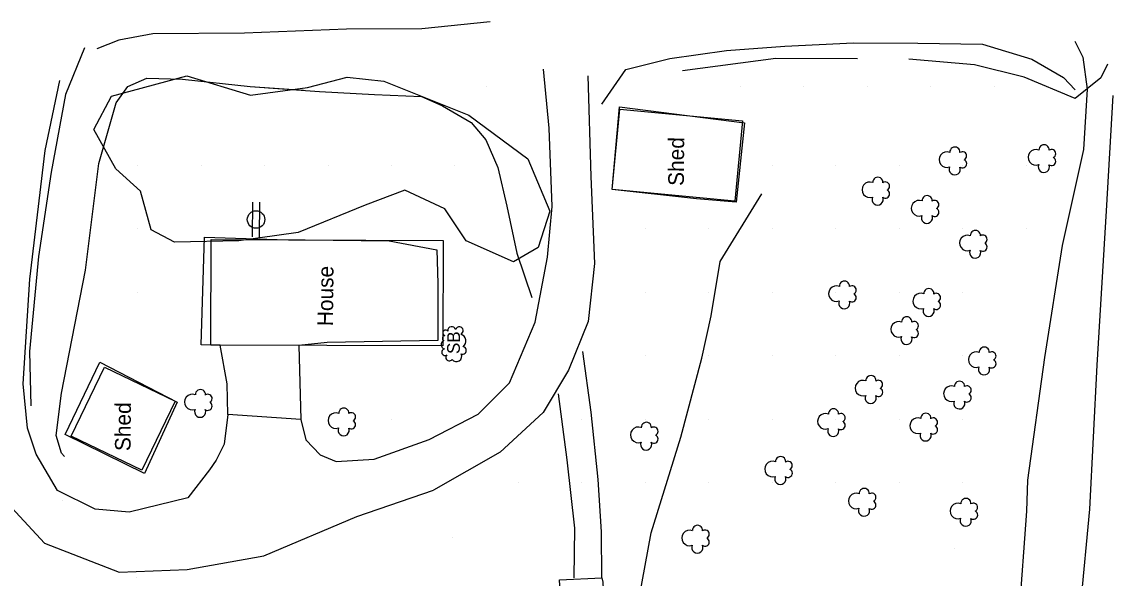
# Model space of a CAD drawing. Extents: x 19528164 to 19545171, y 7585743 to 7602745.
# Drawn here: x 19539508.5 to 19539852.4, y 7595364.9 to 7595540.3 of the extents above; entities that cross this region are included whole.
import ezdxf

# ---------------------------------------------------------------- set-up
doc = ezdxf.new("R2010")
doc.units = 0
for name, color, linetype in [('PhoBreakLine', 7, 'Continuous'), ('PhoBuilding', 7, 'Continuous'), ('PhoDrainageArrow', 7, 'Continuous'), ('PhoEdgeEntrancePaved', 7, 'Continuous'), ('PhoISAEPoints', 7, 'Continuous'), ('PhoNotesDesign', 7, 'Continuous'), ('PhoTerrace', 7, 'Continuous'), ('PhoVegetation', 7, 'Continuous'), ('SurBreakLine', 7, 'Continuous'), ('SurEdgeEntranceUnpaved', 7, 'Continuous'), ('SurNaturalCells', 7, 'Continuous'), ('SurROWRail', 7, 'Continuous')]:
    doc.layers.add(name, color=color, linetype=linetype)

msp = doc.modelspace()

# ---------------------------------------------------------------- linework, layer by layer
at = {"layer": 'PhoBreakLine'}
for points in [[(19539656.14, 7595540.26), (19539634.56, 7595538.05), (19539610.86, 7595537.93), (19539578.71, 7595536.73), (19539549.77, 7595536.45), (19539539.03, 7595534.45), (19539532.18, 7595531.7)], [(19539528.27, 7595532.08), (19539522.26, 7595517.34), (19539517.79, 7595492.87), (19539513.77, 7595466.3), (19539510.93, 7595436.35), (19539511.31, 7595419.16)], [(19539691.32, 7595514.29), (19539698.89, 7595525.2), (19539712.75, 7595528.74), (19539730.58, 7595531.21), (19539748.91, 7595532.55), (19539770.57, 7595533.66), (19539790.89, 7595533.48), (19539811.26, 7595533.17), (19539826.76, 7595528.51), (19539836.79, 7595522.69), (19539840.45, 7595518.84)], [(19539521.95, 7595403.18), (19539520.98, 7595404.28), (19539519.31, 7595409.86), (19539521.01, 7595423.21), (19539528.56, 7595461.98), (19539532.8, 7595495.58), (19539538.26, 7595514.75), (19539541.87, 7595519.9), (19539547.93, 7595522.49), (19539559.17, 7595522.21), (19539580.47, 7595519.88), (19539602.35, 7595518.32), (19539619.61, 7595517.35), (19539634.42, 7595516.76), (19539641.11, 7595513.75), (19539650.09, 7595508.47), (19539654.74, 7595503.08), (19539658.56, 7595494.33), (19539661.33, 7595482.18), (19539664.54, 7595467.32), (19539669.21, 7595453.4)], [(19539521.95, 7595403.18), (19539520.98, 7595404.28), (19539519.31, 7595409.86), (19539521.01, 7595423.21), (19539528.56, 7595461.98), (19539532.8, 7595495.58), (19539538.26, 7595514.75), (19539541.87, 7595519.9), (19539547.93, 7595522.49), (19539559.17, 7595522.21), (19539580.47, 7595519.88), (19539602.35, 7595518.32), (19539619.61, 7595517.35), (19539634.42, 7595516.76), (19539641.11, 7595513.75), (19539650.09, 7595508.47), (19539654.74, 7595503.08), (19539658.56, 7595494.33), (19539661.33, 7595482.18), (19539664.54, 7595467.32), (19539669.21, 7595453.4)], [(19539639.33, 7595468.39), (19539639.58, 7595457.72), (19539639.61, 7595439.84), (19539604.76, 7595439.12), (19539595.78, 7595438.24), (19539571.06, 7595438.33), (19539565.03, 7595438.41), (19539566.04, 7595472.32), (19539588.94, 7595471.63), (19539624.3, 7595471.25), (19539639.33, 7595468.39)]]:
    msp.add_lwpolyline(points, dxfattribs=at)
for points in [[(19539736.23, 7595508.41), (19539733.62, 7595483.44), (19539721.09, 7595484.43), (19539694.59, 7595487.36), (19539696.86, 7595513.43)], [(19539522.2, 7595410.17), (19539533.07, 7595432.93), (19539557.48, 7595420.37), (19539547.13, 7595397.82)], [(19539522.2, 7595410.17), (19539533.07, 7595432.93), (19539557.48, 7595420.37), (19539547.13, 7595397.82)]]:
    msp.add_lwpolyline(points, close=True, dxfattribs=at)
at = {"layer": 'PhoBuilding'}
for points in [[(19539696.96, 7595512.7), (19539735.6, 7595509), (19539733.18, 7595483.67), (19539694.54, 7595487.37)], [(19539568.21, 7595471.63), (19539641.3, 7595471.37), (19539641.18, 7595438.08), (19539568.09, 7595438.34)], [(19539534.59, 7595431.42), (19539556.87, 7595420.63), (19539546.34, 7595398.87), (19539524.05, 7595409.65)], [(19539534.59, 7595431.42), (19539556.87, 7595420.63), (19539546.34, 7595398.87), (19539524.05, 7595409.65)]]:
    msp.add_lwpolyline(points, close=True, dxfattribs=at)
at = {"layer": 'PhoDrainageArrow'}
msp.add_lwpolyline([(19539840.3, 7595534.21), (19539842.9, 7595529.15), (19539844.21, 7595518.99), (19539843.09, 7595500.03), (19539836.39, 7595469.78), (19539830.77, 7595434.44), (19539825.41, 7595395.73), (19539825.08, 7595385.99)], dxfattribs=at)
msp.add_lwpolyline([(19539840.3, 7595534.21), (19539842.9, 7595529.15), (19539844.21, 7595518.99), (19539843.09, 7595500.03), (19539836.39, 7595469.78), (19539830.77, 7595434.44), (19539825.41, 7595395.73), (19539825.08, 7595385.99)], dxfattribs=at)
at = {"layer": 'PhoEdgeEntrancePaved'}
msp.add_lwpolyline([(19539595.78, 7595438.24), (19539596.42, 7595414.85), (19539573.4, 7595416.42), (19539573.23, 7595426.17), (19539571.06, 7595438.33)], dxfattribs=at)
msp.add_lwpolyline([(19539691.58, 7595363.55), (19539692.41, 7595345.9), (19539692.02, 7595329.56), (19539689.73, 7595299.93), (19539673.78, 7595300.14), (19539675.32, 7595315.13), (19539676.3, 7595326.05), (19539678.13, 7595336.3), (19539679.5, 7595338.73), (19539677.96, 7595364.29), (19539691.28, 7595364.99)], close=True, dxfattribs=at)
at = {"layer": 'PhoISAEPoints'}
for p, q in [((19539655, 7595520), (19539655, 7595520)), ((19539735, 7595520), (19539735, 7595520)), ((19539755, 7595520), (19539755, 7595520)), ((19539775, 7595520), (19539775, 7595520)), ((19539795, 7595520), (19539795, 7595520)), ((19539815, 7595520), (19539815, 7595520)), ((19539545, 7595495), (19539545, 7595495)), ((19539565, 7595495), (19539565, 7595495)), ((19539585.04, 7595495), (19539585.04, 7595495)), ((19539605, 7595495), (19539605, 7595495)), ((19539625, 7595495), (19539625, 7595495)), ((19539645, 7595495), (19539645, 7595495)), ((19539745, 7595495), (19539745, 7595495)), ((19539765, 7595495), (19539765, 7595495)), ((19539785, 7595495), (19539785, 7595495)), ((19539805, 7595495), (19539805, 7595495)), ((19539825, 7595495), (19539825, 7595495)), ((19539545, 7595475), (19539545, 7595475)), ((19539705, 7595475), (19539705, 7595475)), ((19539725, 7595475), (19539725, 7595475)), ((19539745, 7595475), (19539745, 7595475)), ((19539765, 7595475), (19539765, 7595475)), ((19539785, 7595475), (19539785, 7595475)), ((19539805, 7595475), (19539805, 7595475)), ((19539825, 7595475), (19539825, 7595475)), ((19539545, 7595455), (19539545, 7595455)), ((19539705, 7595455), (19539705, 7595455)), ((19539725, 7595455), (19539725, 7595455)), ((19539745, 7595455), (19539745, 7595455)), ((19539765, 7595455), (19539765, 7595455)), ((19539785, 7595455), (19539785, 7595455)), ((19539805, 7595455), (19539805, 7595455)), ((19539705, 7595435), (19539705, 7595435)), ((19539725, 7595435), (19539725, 7595435)), ((19539745, 7595435), (19539745, 7595435)), ((19539765, 7595435), (19539765, 7595435)), ((19539785, 7595435), (19539785, 7595435)), ((19539805, 7595435), (19539805, 7595435)), ((19539625, 7595415), (19539625, 7595415)), ((19539685, 7595415), (19539685, 7595415)), ((19539705, 7595415), (19539705, 7595415)), ((19539725, 7595415), (19539725, 7595415)), ((19539745, 7595415), (19539745, 7595415)), ((19539765, 7595415), (19539765, 7595415)), ((19539785, 7595415), (19539785, 7595415)), ((19539805, 7595415), (19539805, 7595415)), ((19539665, 7595395), (19539665, 7595395)), ((19539665, 7595395), (19539665, 7595395)), ((19539685, 7595395), (19539685, 7595395)), ((19539685, 7595395), (19539685, 7595395)), ((19539705, 7595395), (19539705, 7595395)), ((19539705, 7595395), (19539705, 7595395)), ((19539725, 7595395), (19539725, 7595395)), ((19539725, 7595395), (19539725, 7595395)), ((19539745, 7595395), (19539745, 7595395)), ((19539745, 7595395), (19539745, 7595395)), ((19539765, 7595395), (19539765, 7595395)), ((19539765, 7595395), (19539765, 7595395)), ((19539785, 7595395), (19539785, 7595395)), ((19539785, 7595395), (19539785, 7595395)), ((19539805, 7595395), (19539805, 7595395))]:
    msp.add_line(p, q, dxfattribs=at)
at = {"layer": 'PhoTerrace'}
msp.add_lwpolyline([(19539845.06, 7595386.63), (19539847.38, 7595432.02), (19539850.38, 7595480.63), (19539852.43, 7595517.07)], dxfattribs=at)
msp.add_lwpolyline([(19539845.06, 7595386.63), (19539847.38, 7595432.02), (19539850.38, 7595480.63), (19539852.43, 7595517.07)], dxfattribs=at)
at = {"layer": 'PhoVegetation'}
for points in [[(19539771.9, 7595528.63), (19539746.11, 7595528.67), (19539716.68, 7595524.86)], [(19539850.63, 7595526.9), (19539848.56, 7595522.56), (19539840.48, 7595516.06), (19539824.35, 7595522.83), (19539808.7, 7595526.71), (19539788.03, 7595528.51)]]:
    msp.add_lwpolyline(points, dxfattribs=at)
msp.add_lwpolyline([(19539622.6, 7595521.55), (19539649.43, 7595510.88), (19539668.01, 7595497.04), (19539674.87, 7595480.6), (19539671.27, 7595469.15), (19539663.47, 7595464.57), (19539648.52, 7595471.24), (19539641.79, 7595481.29), (19539629.19, 7595487.19), (19539616.71, 7595482.5), (19539595.57, 7595473.81), (19539576.91, 7595471.17), (19539556.66, 7595470.78), (19539549.24, 7595474.73), (19539545.86, 7595486.88), (19539538.13, 7595493.93), (19539531.21, 7595506.26), (19539536.77, 7595516.81), (19539560.46, 7595523.19), (19539580.62, 7595517.16), (19539598.49, 7595519.59), (19539611.08, 7595522.83)], close=True, dxfattribs=at)
for centre, radius, start, end in [((19539830.64, 7595499.91), 1.6, 355.2463, 183.2499), ((19539800.02, 7595496.82), 2.46, 67.4531, 291.043), ((19539802.56, 7595499.19), 1.6, 355.2463, 183.2499), ((19539804.92, 7595497.95), 1.34, 295.7722, 124.6514), ((19539828.09, 7595497.55), 2.46, 67.4531, 291.043), ((19539833, 7595496.26), 1.34, 231.9982, 64.5704), ((19539833, 7595498.68), 1.34, 295.7722, 124.6514), ((19539802.49, 7595493.77), 1.76, 154.7305, 23.7656), ((19539804.93, 7595495.54), 1.34, 231.9982, 64.5704), ((19539830.57, 7595494.5), 1.76, 154.7305, 23.7656), ((19539778.28, 7595489.67), 1.6, 355.2463, 183.2499), ((19539775.74, 7595487.3), 2.46, 67.4531, 291.043), ((19539780.64, 7595486.02), 1.34, 231.9982, 64.5704), ((19539780.64, 7595488.44), 1.34, 295.7722, 124.6514), ((19539778.21, 7595484.26), 1.76, 154.7305, 23.7656), ((19539791.27, 7595481.5), 2.46, 67.4531, 291.043), ((19539793.81, 7595483.87), 1.6, 355.2463, 183.2499), ((19539796.17, 7595482.64), 1.34, 295.7722, 124.6514), ((19539796.17, 7595480.22), 1.34, 231.9982, 64.5704), ((19539793.74, 7595478.46), 1.76, 154.7305, 23.7656), ((19539809.01, 7595472.91), 1.6, 355.2463, 183.2499), ((19539806.47, 7595470.55), 2.46, 67.4531, 291.043), ((19539811.38, 7595469.27), 1.34, 231.9982, 64.5704), ((19539811.37, 7595471.68), 1.34, 295.7722, 124.6514), ((19539808.94, 7595467.5), 1.76, 154.7305, 23.7656), ((19539765.21, 7595454.57), 2.46, 67.4531, 291.043), ((19539767.75, 7595456.93), 1.6, 355.2463, 183.2499), ((19539770.11, 7595455.7), 1.34, 295.7722, 124.6514), ((19539794.35, 7595454.57), 1.6, 355.2463, 183.2499), ((19539770.12, 7595453.29), 1.34, 231.9982, 64.5704), ((19539791.8, 7595452.21), 2.46, 67.4531, 291.043), ((19539796.7, 7595453.34), 1.34, 295.7722, 124.6514), ((19539767.68, 7595451.52), 1.76, 154.7305, 23.7656), ((19539794.27, 7595449.16), 1.76, 154.7305, 23.7656), ((19539796.71, 7595450.93), 1.34, 231.9982, 64.5704), ((19539784.83, 7595443.32), 2.46, 67.4531, 291.043), ((19539787.37, 7595445.68), 1.6, 355.2463, 183.2499), ((19539789.73, 7595444.45), 1.34, 295.7722, 124.6514), ((19539642.05, 7595442.19), 0.9, 40.6417, 255.6594), ((19539644.03, 7595442.86), 1.3, 20.1519, 183.6168), ((19539646.37, 7595442.87), 1.21, 294.0775, 159.1351), ((19539789.74, 7595442.04), 1.34, 231.9982, 64.5704), ((19539642.05, 7595438.48), 1.41, 111.8517, 255.0316), ((19539641.82, 7595440.52), 0.794, 89.7085, 248.0319), ((19539646.2, 7595439.6), 2.27, 309.2663, 72.9457), ((19539787.3, 7595440.27), 1.76, 154.7305, 23.7656), ((19539641.86, 7595436.1), 1.04, 99.8428, 303.6092), ((19539645.47, 7595434.81), 1.67, 215.0769, 28.5329), ((19539647.41, 7595436.69), 1.18, 246.2738, 79.0083), ((19539809.26, 7595433.75), 2.46, 67.4531, 291.043), ((19539811.81, 7595436.11), 1.6, 355.2463, 183.2499), ((19539814.17, 7595434.88), 1.34, 295.7722, 124.6514), ((19539643.2, 7595434.46), 1.09, 134.5935, 326.0554), ((19539814.17, 7595432.47), 1.34, 231.9982, 64.5704), ((19539776.1, 7595427.14), 1.6, 355.2463, 183.2499), ((19539811.74, 7595430.7), 1.76, 154.7305, 23.7656), ((19539773.55, 7595424.77), 2.46, 67.4531, 291.043), ((19539778.45, 7595425.91), 1.34, 295.7722, 124.6514), ((19539801.47, 7595423.01), 2.46, 67.4531, 291.043), ((19539804.02, 7595425.37), 1.6, 355.2463, 183.2499), ((19539806.37, 7595424.14), 1.34, 295.7722, 124.6514), ((19539562.24, 7595420.38), 2.46, 67.4531, 291.043), ((19539564.79, 7595422.74), 1.6, 355.2463, 183.2499), ((19539567.15, 7595421.51), 1.34, 295.7722, 124.6514), ((19539776.03, 7595421.73), 1.76, 154.7305, 23.7656), ((19539778.46, 7595423.49), 1.34, 231.9982, 64.5704), ((19539806.38, 7595421.73), 1.34, 231.9982, 64.5704), ((19539567.15, 7595419.1), 1.34, 231.9982, 64.5704), ((19539610, 7595416.9), 1.6, 355.2463, 183.2499), ((19539764.3, 7595416.67), 1.6, 355.2463, 183.2499), ((19539803.95, 7595419.96), 1.76, 154.7305, 23.7656), ((19539564.72, 7595417.33), 1.76, 154.7305, 23.7656), ((19539607.46, 7595414.54), 2.46, 67.4531, 291.043), ((19539612.36, 7595415.67), 1.34, 295.7722, 124.6514), ((19539761.75, 7595414.31), 2.46, 67.4531, 291.043), ((19539766.65, 7595415.44), 1.34, 295.7722, 124.6514), ((19539790.85, 7595412.92), 2.46, 67.4531, 291.043), ((19539793.39, 7595415.28), 1.6, 355.2463, 183.2499), ((19539795.75, 7595414.05), 1.34, 295.7722, 124.6514), ((19539609.93, 7595411.49), 1.76, 154.7305, 23.7656), ((19539612.36, 7595413.26), 1.34, 231.9982, 64.5704), ((19539702.77, 7595410.04), 2.46, 67.4531, 291.043), ((19539705.32, 7595412.4), 1.6, 355.2463, 183.2499), ((19539707.68, 7595411.17), 1.34, 295.7722, 124.6514), ((19539764.22, 7595411.26), 1.76, 154.7305, 23.7656), ((19539766.66, 7595413.02), 1.34, 231.9982, 64.5704), ((19539795.76, 7595411.64), 1.34, 231.9982, 64.5704), ((19539707.68, 7595408.75), 1.34, 231.9982, 64.5704), ((19539793.32, 7595409.87), 1.76, 154.7305, 23.7656), ((19539705.25, 7595406.99), 1.76, 154.7305, 23.7656), ((19539745.08, 7595399.25), 2.46, 67.4531, 291.043), ((19539745.08, 7595399.25), 2.46, 67.4531, 291.043), ((19539747.63, 7595401.61), 1.6, 355.2463, 183.2499), ((19539747.63, 7595401.61), 1.6, 355.2463, 183.2499), ((19539749.98, 7595400.38), 1.34, 295.7722, 124.6514), ((19539749.98, 7595400.38), 1.34, 295.7722, 124.6514), ((19539749.99, 7595397.97), 1.34, 231.9982, 64.5704), ((19539749.99, 7595397.97), 1.34, 231.9982, 64.5704), ((19539747.55, 7595396.2), 1.76, 154.7305, 23.7656), ((19539747.55, 7595396.2), 1.76, 154.7305, 23.7656), ((19539771.44, 7595389.2), 2.46, 67.4531, 291.043), ((19539771.44, 7595389.2), 2.46, 67.4531, 291.043), ((19539773.99, 7595391.56), 1.6, 355.2463, 183.2499), ((19539773.99, 7595391.56), 1.6, 355.2463, 183.2499), ((19539776.34, 7595390.33), 1.34, 295.7722, 124.6514), ((19539776.34, 7595390.33), 1.34, 295.7722, 124.6514), ((19539776.35, 7595387.92), 1.34, 231.9982, 64.5704), ((19539776.35, 7595387.92), 1.34, 231.9982, 64.5704), ((19539803.49, 7595386.04), 2.46, 67.4531, 291.043), ((19539806.03, 7595388.41), 1.6, 355.2463, 183.2499), ((19539808.39, 7595387.17), 1.34, 295.7722, 124.6514), ((19539773.91, 7595386.15), 1.76, 154.7305, 23.7656), ((19539773.91, 7595386.15), 1.76, 154.7305, 23.7656), ((19539808.4, 7595384.76), 1.34, 231.9982, 64.5704), ((19539721.46, 7595379.93), 1.6, 355.2463, 183.2499), ((19539805.96, 7595383), 1.76, 154.7305, 23.7656), ((19539718.92, 7595377.56), 2.46, 67.4531, 291.043), ((19539723.82, 7595376.28), 1.34, 231.9982, 64.5704), ((19539723.82, 7595378.69), 1.34, 295.7722, 124.6514), ((19539721.39, 7595374.52), 1.76, 154.7305, 23.7656)]:
    msp.add_arc(centre, radius, start, end, dxfattribs=at)
at = {"layer": 'SurBreakLine'}
for points in [[(19539840.3, 7595534.21), (19539842.9, 7595529.15), (19539844.21, 7595518.99), (19539843.09, 7595500.03), (19539836.39, 7595469.78), (19539830.77, 7595434.44), (19539825.41, 7595395.73), (19539825.08, 7595385.99)], [(19539521.95, 7595403.18), (19539520.98, 7595404.28), (19539519.31, 7595409.86), (19539521.01, 7595423.21), (19539528.56, 7595461.98), (19539532.8, 7595495.58), (19539538.26, 7595514.75), (19539541.87, 7595519.9), (19539547.93, 7595522.49), (19539559.17, 7595522.21), (19539580.47, 7595519.88), (19539597.26, 7595518.68)], [(19539845.06, 7595386.63), (19539847.38, 7595432.02), (19539850.38, 7595480.63), (19539852.43, 7595517.07)], [(19539702.3, 7595318.13), (19539700.95, 7595347.07), (19539706.8, 7595379.19), (19539716.15, 7595409.28), (19539722.76, 7595434.24), (19539725.77, 7595447.54), (19539728.58, 7595464.72), (19539741.69, 7595486.07)], [(19539573.4, 7595416.42), (19539572.23, 7595407.08), (19539569.76, 7595402.08), (19539567.67, 7595399.02)], [(19539825.08, 7595385.99), (19539822.75, 7595352.96), (19539821.71, 7595273.61), (19539817.74, 7595207.38), (19539816.4, 7595164.27), (19539818.83, 7595146.42)], [(19539831, 7595141.37), (19539837.69, 7595218.67), (19539840.34, 7595295.59), (19539842.26, 7595356.59), (19539845.06, 7595386.63)]]:
    msp.add_lwpolyline(points, dxfattribs=at)
msp.add_lwpolyline([(19539522.2, 7595410.17), (19539533.07, 7595432.93), (19539557.48, 7595420.37), (19539547.13, 7595397.82)], close=True, dxfattribs=at)
at = {"layer": 'SurEdgeEntranceUnpaved'}
for p, q in [((19539665, 7595395), (19539665, 7595395)), ((19539685, 7595395), (19539685, 7595395)), ((19539705, 7595395), (19539705, 7595395)), ((19539725, 7595395), (19539725, 7595395)), ((19539745, 7595395), (19539745, 7595395)), ((19539765, 7595395), (19539765, 7595395)), ((19539785, 7595395), (19539785, 7595395)), ((19539521.28, 7595389.49), (19539521.28, 7595389.49)), ((19539644.2, 7595377.55), (19539644.2, 7595377.55)), ((19539802.53, 7595374.13), (19539802.53, 7595374.13)), ((19539544.63, 7595365.09), (19539544.63, 7595365.09))]:
    msp.add_line(p, q, dxfattribs=at)
at = {"layer": 'SurNaturalCells'}
for p, q in [((19539581.16, 7595472.44), (19539581.3, 7595483.43)), ((19539583.36, 7595472.41), (19539583.5, 7595483.4))]:
    msp.add_line(p, q, dxfattribs=at)
msp.add_circle((19539582.33, 7595477.92), 2.76, dxfattribs=at)
at = {"layer": 'SurROWRail'}
for points in [[(19539596.42, 7595414.85), (19539598, 7595408.49), (19539602.57, 7595403.71), (19539607.61, 7595401.63), (19539619.56, 7595402.43), (19539636.86, 7595408.55), (19539652.31, 7595416.56), (19539662.24, 7595426.44), (19539670.31, 7595445.62), (19539674.12, 7595466.11), (19539675.6, 7595482.05), (19539674.7, 7595506.72), (19539672.88, 7595525.33)], [(19539596.42, 7595414.85), (19539598, 7595408.49), (19539602.57, 7595403.71), (19539607.61, 7595401.63), (19539619.56, 7595402.43), (19539636.86, 7595408.55), (19539652.31, 7595416.56), (19539662.24, 7595426.44), (19539670.31, 7595445.62), (19539674.12, 7595466.11), (19539675.6, 7595482.05), (19539674.7, 7595506.72), (19539672.88, 7595525.33)], [(19539513.01, 7595404), (19539510.28, 7595412.13), (19539508.89, 7595426.18), (19539511.03, 7595459.16), (19539515.85, 7595499.67), (19539520.51, 7595521.77)], [(19539513.01, 7595404), (19539510.28, 7595412.13), (19539508.89, 7595426.18), (19539511.03, 7595459.16), (19539515.85, 7595499.67), (19539520.51, 7595521.77)], [(19539686.93, 7595523.21), (19539687.78, 7595491.46), (19539689, 7595464.08), (19539687.01, 7595445.75), (19539680.74, 7595430.44), (19539672.78, 7595417.04), (19539659.24, 7595404.54), (19539638.23, 7595392.61)], [(19539686.93, 7595523.21), (19539687.78, 7595491.46), (19539689, 7595464.08), (19539687.01, 7595445.75), (19539680.74, 7595430.44), (19539672.78, 7595417.04), (19539659.24, 7595404.54), (19539638.23, 7595392.61)], [(19539691.28, 7595364.99), (19539691.17, 7595379.44), (19539690.16, 7595395.97), (19539687.98, 7595417.2), (19539685.35, 7595436.34)], [(19539682.59, 7595364.93), (19539682.79, 7595380.6), (19539680.38, 7595402.16), (19539677.66, 7595423.02)], [(19539573.4, 7595416.42), (19539572.23, 7595407.08), (19539569.76, 7595402.08), (19539567.67, 7595399.02)], [(19539573.4, 7595416.42), (19539572.23, 7595407.08), (19539569.76, 7595402.08), (19539567.67, 7595399.02)], [(19539494.02, 7595407.99), (19539502.74, 7595389.83), (19539515.61, 7595375.88), (19539539.21, 7595366.78), (19539560.58, 7595367.6), (19539584.8, 7595371.9), (19539614.09, 7595384.27), (19539638.23, 7595392.61)], [(19539567.67, 7595399.02), (19539560.86, 7595390.18), (19539542.32, 7595385.66), (19539531.64, 7595386.59), (19539519.8, 7595392.48), (19539513.01, 7595404)]]:
    msp.add_lwpolyline(points, dxfattribs=at)

# ---------------------------------------------------------------- texts
at = {"layer": 'PhoNotesDesign'}
for s, p in [('Shed', (19539717.13, 7595488.53)), ('House', (19539606.58, 7595444.29)), ('Shed', (19539542.78, 7595404.92)), ('Shed', (19539542.78, 7595404.92))]:
    msp.add_text(s, height=4.92, rotation=89.5617, dxfattribs=at).set_placement(p)
at = {"layer": 'PhoVegetation'}
msp.add_text('SB', height=3.999, rotation=89.2481, dxfattribs=at).set_placement((19539646.51, 7595435.52))

doc.saveas('drawing.dxf')
